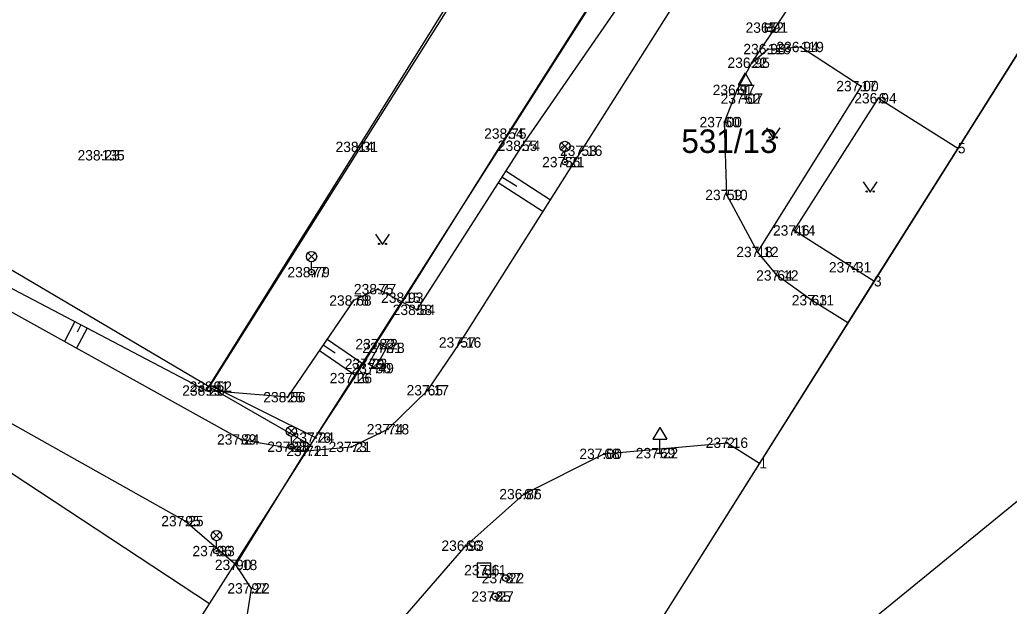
# Model space of a CAD drawing. Extents: x -645398 to -644998, y -1063322 to -1063031.
# Drawn here: x -645269.4 to -645197.8, y -1063193.6 to -1063151.2 of the extents above; entities that cross this region are included whole.
import ezdxf

# ---------------------------------------------------------------- set-up
doc = ezdxf.new("R2010")
doc.units = 0
for name, color, linetype in [('Bod', 7, 'Continuous'), ('Doplněk polohopisu', 7, 'Continuous'), ('Elektrický kabel', 7, 'Continuous'), ('Hranice KN pozemků', 7, 'Continuous'), ('Kanalizace', 7, 'Continuous'), ('Kultury', 7, 'Continuous'), ('Rozhraní ploch', 7, 'Continuous'), ('Stavby', 7, 'Continuous'), ('Sítě podzemní nerozlišené', 7, 'Continuous'), ('Vjezdy-vchody', 7, 'Continuous'), ('Výška', 7, 'Continuous'), ('Výškopis', 7, 'Continuous'), ('Čísla parcel', 7, 'Continuous'), ('Číslo bodu', 7, 'Continuous'), ('Šrafy', 7, 'Continuous')]:
    doc.layers.add(name, color=color, linetype=linetype)

msp = doc.modelspace()

# ---------------------------------------------------------------- linework, layer by layer
at = {"layer": 'Bod'}
for p, q in [((-645215.22, -1063151.75), (-645215.27, -1063151.7)), ((-645215.22, -1063151.75), (-645215.27, -1063151.8)), ((-645215.22, -1063151.75), (-645215.17, -1063151.7)), ((-645215.22, -1063151.75), (-645215.17, -1063151.8)), ((-645215.29, -1063153.3), (-645215.34, -1063153.25)), ((-645215.29, -1063153.3), (-645215.24, -1063153.25)), ((-645212.9, -1063153.15), (-645212.95, -1063153.1)), ((-645212.9, -1063153.15), (-645212.95, -1063153.2)), ((-645212.9, -1063153.15), (-645212.85, -1063153.1)), ((-645212.9, -1063153.15), (-645212.85, -1063153.2)), ((-645215.29, -1063153.3), (-645215.34, -1063153.35)), ((-645215.29, -1063153.3), (-645215.24, -1063153.35)), ((-645216.44, -1063154.29), (-645216.49, -1063154.24)), ((-645216.44, -1063154.29), (-645216.49, -1063154.34)), ((-645216.44, -1063154.29), (-645216.39, -1063154.24)), ((-645216.44, -1063154.29), (-645216.39, -1063154.34)), ((-645208.52, -1063155.98), (-645208.57, -1063155.93)), ((-645208.52, -1063155.98), (-645208.57, -1063156.03)), ((-645208.52, -1063155.98), (-645208.47, -1063155.93)), ((-645208.52, -1063155.98), (-645208.47, -1063156.03)), ((-645217.51, -1063156.26), (-645217.56, -1063156.21)), ((-645217.51, -1063156.26), (-645217.56, -1063156.31)), ((-645217.51, -1063156.26), (-645217.46, -1063156.21)), ((-645217.51, -1063156.26), (-645217.46, -1063156.31)), ((-645216.93, -1063156.89), (-645216.98, -1063156.84)), ((-645216.93, -1063156.89), (-645216.88, -1063156.84)), ((-645207.26, -1063156.86), (-645207.31, -1063156.81)), ((-645207.26, -1063156.86), (-645207.21, -1063156.81)), ((-645216.93, -1063156.89), (-645216.98, -1063156.94)), ((-645216.93, -1063156.89), (-645216.88, -1063156.94)), ((-645207.26, -1063156.86), (-645207.31, -1063156.91)), ((-645207.26, -1063156.86), (-645207.21, -1063156.91)), ((-645218.42, -1063158.59), (-645218.47, -1063158.54)), ((-645218.42, -1063158.59), (-645218.47, -1063158.64)), ((-645218.42, -1063158.59), (-645218.37, -1063158.54)), ((-645218.42, -1063158.59), (-645218.37, -1063158.64)), ((-645234.08, -1063159.42), (-645234.13, -1063159.37)), ((-645234.08, -1063159.42), (-645234.13, -1063159.47)), ((-645234.08, -1063159.42), (-645234.03, -1063159.37)), ((-645234.08, -1063159.42), (-645234.03, -1063159.47)), ((-645244.93, -1063160.38), (-645244.98, -1063160.33)), ((-645244.93, -1063160.38), (-645244.98, -1063160.43)), ((-645244.93, -1063160.38), (-645244.88, -1063160.33)), ((-645244.93, -1063160.38), (-645244.88, -1063160.43)), ((-645233.09, -1063160.3), (-645233.14, -1063160.25)), ((-645233.09, -1063160.3), (-645233.14, -1063160.35)), ((-645233.09, -1063160.3), (-645233.04, -1063160.25)), ((-645233.09, -1063160.3), (-645233.04, -1063160.35)), ((-645201.53, -1063160.47), (-645201.58, -1063160.42)), ((-645201.53, -1063160.47), (-645201.48, -1063160.42)), ((-645263.52, -1063160.99), (-645263.57, -1063160.94)), ((-645263.52, -1063160.99), (-645263.57, -1063161.04)), ((-645263.52, -1063160.99), (-645263.47, -1063160.94)), ((-645263.52, -1063160.99), (-645263.47, -1063161.04)), ((-645228.78, -1063160.66), (-645228.83, -1063160.61)), ((-645228.78, -1063160.66), (-645228.83, -1063160.71)), ((-645228.78, -1063160.66), (-645228.73, -1063160.61)), ((-645228.78, -1063160.66), (-645228.73, -1063160.71)), ((-645201.53, -1063160.47), (-645201.58, -1063160.52)), ((-645201.53, -1063160.47), (-645201.48, -1063160.52)), ((-645229.97, -1063161.48), (-645230.02, -1063161.43)), ((-645229.97, -1063161.48), (-645230.02, -1063161.53)), ((-645229.97, -1063161.48), (-645229.92, -1063161.43)), ((-645229.97, -1063161.48), (-645229.92, -1063161.53)), ((-645218.25, -1063163.86), (-645218.3, -1063163.81)), ((-645218.25, -1063163.86), (-645218.3, -1063163.91)), ((-645218.25, -1063163.86), (-645218.2, -1063163.81)), ((-645218.25, -1063163.86), (-645218.2, -1063163.91)), ((-645213.38, -1063166.43), (-645213.43, -1063166.38)), ((-645213.38, -1063166.43), (-645213.43, -1063166.48)), ((-645213.38, -1063166.43), (-645213.33, -1063166.38)), ((-645213.38, -1063166.43), (-645213.33, -1063166.48)), ((-645216.04, -1063167.99), (-645216.09, -1063167.94)), ((-645216.04, -1063167.99), (-645216.09, -1063168.04)), ((-645216.04, -1063167.99), (-645215.99, -1063167.94)), ((-645216.04, -1063167.99), (-645215.99, -1063168.04)), ((-645248.32, -1063169.45), (-645248.37, -1063169.4)), ((-645248.32, -1063169.45), (-645248.37, -1063169.5)), ((-645248.32, -1063169.45), (-645248.27, -1063169.4)), ((-645248.32, -1063169.45), (-645248.27, -1063169.5)), ((-645214.6, -1063169.69), (-645214.65, -1063169.64)), ((-645214.6, -1063169.69), (-645214.65, -1063169.74)), ((-645214.6, -1063169.69), (-645214.55, -1063169.64)), ((-645214.6, -1063169.69), (-645214.55, -1063169.74)), ((-645209.21, -1063169.1), (-645209.26, -1063169.05)), ((-645209.21, -1063169.1), (-645209.26, -1063169.15)), ((-645209.21, -1063169.1), (-645209.16, -1063169.05)), ((-645209.21, -1063169.1), (-645209.16, -1063169.15)), ((-645207.6, -1063170.11), (-645207.65, -1063170.06)), ((-645207.6, -1063170.11), (-645207.65, -1063170.16)), ((-645207.6, -1063170.11), (-645207.55, -1063170.06)), ((-645207.6, -1063170.11), (-645207.55, -1063170.16)), ((-645243.51, -1063170.68), (-645243.56, -1063170.63)), ((-645243.51, -1063170.68), (-645243.56, -1063170.73)), ((-645243.51, -1063170.68), (-645243.46, -1063170.63)), ((-645243.51, -1063170.68), (-645243.46, -1063170.73)), ((-645245.27, -1063171.5), (-645245.32, -1063171.45)), ((-645245.27, -1063171.5), (-645245.32, -1063171.55)), ((-645245.27, -1063171.5), (-645245.22, -1063171.45)), ((-645245.27, -1063171.5), (-645245.22, -1063171.55)), ((-645241.54, -1063171.3), (-645241.59, -1063171.25)), ((-645241.54, -1063171.3), (-645241.59, -1063171.35)), ((-645241.54, -1063171.3), (-645241.49, -1063171.25)), ((-645241.54, -1063171.3), (-645241.49, -1063171.35)), ((-645212.11, -1063171.48), (-645212.16, -1063171.43)), ((-645212.11, -1063171.48), (-645212.16, -1063171.53)), ((-645212.11, -1063171.48), (-645212.06, -1063171.43)), ((-645212.11, -1063171.48), (-645212.06, -1063171.53)), ((-645240.7, -1063172.18), (-645240.75, -1063172.13)), ((-645240.7, -1063172.18), (-645240.75, -1063172.23)), ((-645240.7, -1063172.18), (-645240.65, -1063172.13)), ((-645240.7, -1063172.18), (-645240.65, -1063172.23)), ((-645243.4, -1063174.66), (-645243.45, -1063174.61)), ((-645243.4, -1063174.66), (-645243.45, -1063174.71)), ((-645243.4, -1063174.66), (-645243.35, -1063174.61)), ((-645243.4, -1063174.66), (-645243.35, -1063174.71)), ((-645237.55, -1063174.54), (-645237.6, -1063174.49)), ((-645237.55, -1063174.54), (-645237.6, -1063174.59)), ((-645237.55, -1063174.54), (-645237.5, -1063174.49)), ((-645237.55, -1063174.54), (-645237.5, -1063174.59)), ((-645242.9, -1063174.93), (-645242.95, -1063174.88)), ((-645242.9, -1063174.93), (-645242.95, -1063174.98)), ((-645242.9, -1063174.93), (-645242.85, -1063174.88)), ((-645242.9, -1063174.93), (-645242.85, -1063174.98)), ((-645244.17, -1063176.09), (-645244.22, -1063176.04)), ((-645244.17, -1063176.09), (-645244.22, -1063176.14)), ((-645244.17, -1063176.09), (-645244.12, -1063176.04)), ((-645244.17, -1063176.09), (-645244.12, -1063176.14)), ((-645243.68, -1063176.4), (-645243.73, -1063176.35)), ((-645243.68, -1063176.4), (-645243.73, -1063176.45)), ((-645243.68, -1063176.4), (-645243.63, -1063176.35)), ((-645243.68, -1063176.4), (-645243.63, -1063176.45)), ((-645245.24, -1063177.12), (-645245.29, -1063177.07)), ((-645245.24, -1063177.12), (-645245.29, -1063177.17)), ((-645245.24, -1063177.12), (-645245.19, -1063177.07)), ((-645245.24, -1063177.12), (-645245.19, -1063177.17)), ((-645255.94, -1063178.02), (-645255.99, -1063177.97)), ((-645255.94, -1063178.02), (-645255.99, -1063178.07)), ((-645255.94, -1063178.02), (-645255.89, -1063177.97)), ((-645255.94, -1063178.02), (-645255.89, -1063178.07)), ((-645255.41, -1063177.74), (-645255.46, -1063177.69)), ((-645255.41, -1063177.74), (-645255.46, -1063177.79)), ((-645255.41, -1063177.74), (-645255.36, -1063177.69)), ((-645255.41, -1063177.74), (-645255.36, -1063177.79)), ((-645239.91, -1063178), (-645239.96, -1063177.95)), ((-645239.91, -1063178), (-645239.96, -1063178.05)), ((-645239.91, -1063178), (-645239.86, -1063177.95)), ((-645239.91, -1063178), (-645239.86, -1063178.05)), ((-645250.05, -1063178.5), (-645250.1, -1063178.45)), ((-645250.05, -1063178.5), (-645250.1, -1063178.55)), ((-645250.05, -1063178.5), (-645250, -1063178.45)), ((-645250.05, -1063178.5), (-645250, -1063178.55)), ((-645242.79, -1063180.82), (-645242.84, -1063180.77)), ((-645242.79, -1063180.82), (-645242.84, -1063180.87)), ((-645242.79, -1063180.82), (-645242.74, -1063180.77)), ((-645242.79, -1063180.82), (-645242.74, -1063180.87)), ((-645253.42, -1063181.56), (-645253.47, -1063181.51)), ((-645253.42, -1063181.56), (-645253.47, -1063181.61)), ((-645253.42, -1063181.56), (-645253.37, -1063181.51)), ((-645253.42, -1063181.56), (-645253.37, -1063181.61)), ((-645248.02, -1063181.43), (-645248.07, -1063181.38)), ((-645248.02, -1063181.43), (-645248.07, -1063181.48)), ((-645248.02, -1063181.43), (-645247.97, -1063181.38)), ((-645248.02, -1063181.43), (-645247.97, -1063181.48)), ((-645218.23, -1063181.8), (-645218.28, -1063181.75)), ((-645218.23, -1063181.8), (-645218.28, -1063181.85)), ((-645218.23, -1063181.8), (-645218.18, -1063181.75)), ((-645218.23, -1063181.8), (-645218.18, -1063181.85)), ((-645249.78, -1063182.09), (-645249.83, -1063182.04)), ((-645249.78, -1063182.09), (-645249.83, -1063182.14)), ((-645249.78, -1063182.09), (-645249.73, -1063182.04)), ((-645249.78, -1063182.09), (-645249.73, -1063182.14)), ((-645248.71, -1063182.39), (-645248.76, -1063182.34)), ((-645248.71, -1063182.39), (-645248.76, -1063182.44)), ((-645248.71, -1063182.39), (-645248.66, -1063182.34)), ((-645248.71, -1063182.39), (-645248.66, -1063182.44)), ((-645245.43, -1063182.1), (-645245.48, -1063182.05)), ((-645245.43, -1063182.1), (-645245.48, -1063182.15)), ((-645245.43, -1063182.1), (-645245.38, -1063182.05)), ((-645245.43, -1063182.1), (-645245.38, -1063182.15)), ((-645227.12, -1063182.6), (-645227.17, -1063182.55)), ((-645227.12, -1063182.6), (-645227.17, -1063182.65)), ((-645227.12, -1063182.6), (-645227.07, -1063182.55)), ((-645227.12, -1063182.6), (-645227.07, -1063182.65)), ((-645223.1, -1063182.55), (-645223.15, -1063182.5)), ((-645223.1, -1063182.55), (-645223.15, -1063182.6)), ((-645223.1, -1063182.55), (-645223.05, -1063182.5)), ((-645223.1, -1063182.55), (-645223.05, -1063182.6)), ((-645215.89, -1063183.28), (-645215.94, -1063183.23)), ((-645215.89, -1063183.28), (-645215.94, -1063183.33)), ((-645215.89, -1063183.28), (-645215.84, -1063183.23)), ((-645215.89, -1063183.28), (-645215.84, -1063183.33)), ((-645232.94, -1063185.52), (-645232.99, -1063185.47)), ((-645232.94, -1063185.52), (-645232.89, -1063185.47)), ((-645232.94, -1063185.52), (-645232.99, -1063185.57)), ((-645232.94, -1063185.52), (-645232.89, -1063185.57)), ((-645257.46, -1063187.47), (-645257.51, -1063187.42)), ((-645257.46, -1063187.47), (-645257.51, -1063187.52)), ((-645257.46, -1063187.47), (-645257.41, -1063187.42)), ((-645257.46, -1063187.47), (-645257.41, -1063187.52)), ((-645255.2, -1063189.64), (-645255.25, -1063189.59)), ((-645255.2, -1063189.64), (-645255.25, -1063189.69)), ((-645255.2, -1063189.64), (-645255.15, -1063189.59)), ((-645255.2, -1063189.64), (-645255.15, -1063189.69)), ((-645237.15, -1063189.25), (-645237.2, -1063189.2)), ((-645237.15, -1063189.25), (-645237.2, -1063189.3)), ((-645237.15, -1063189.25), (-645237.1, -1063189.2)), ((-645237.15, -1063189.25), (-645237.1, -1063189.3)), ((-645253.79, -1063190.64), (-645253.84, -1063190.59)), ((-645253.79, -1063190.64), (-645253.84, -1063190.69)), ((-645253.79, -1063190.64), (-645253.74, -1063190.59)), ((-645253.79, -1063190.64), (-645253.74, -1063190.69)), ((-645235.83, -1063191.02), (-645235.88, -1063190.97)), ((-645235.83, -1063191.02), (-645235.88, -1063191.07)), ((-645235.83, -1063191.02), (-645235.78, -1063190.97)), ((-645235.83, -1063191.02), (-645235.78, -1063191.07)), ((-645234.25, -1063191.6), (-645234.3, -1063191.55)), ((-645234.25, -1063191.6), (-645234.3, -1063191.65)), ((-645234.25, -1063191.6), (-645234.2, -1063191.55)), ((-645234.25, -1063191.6), (-645234.2, -1063191.65)), ((-645252.67, -1063192.34), (-645252.72, -1063192.29)), ((-645252.67, -1063192.34), (-645252.72, -1063192.39)), ((-645252.67, -1063192.34), (-645252.62, -1063192.29)), ((-645252.67, -1063192.34), (-645252.62, -1063192.39)), ((-645235, -1063192.93), (-645235.05, -1063192.88)), ((-645235, -1063192.93), (-645235.05, -1063192.98)), ((-645235, -1063192.93), (-645234.95, -1063192.88)), ((-645235, -1063192.93), (-645234.95, -1063192.98))]:
    msp.add_line(p, q, dxfattribs=at)
at = {"layer": 'Doplněk polohopisu'}
for p, q in [((-645216.93, -1063155.024), (-645217.43, -1063155.89)), ((-645216.93, -1063155.024), (-645216.43, -1063155.89)), ((-645217.43, -1063155.89), (-645216.43, -1063155.89)), ((-645216.93, -1063156.89), (-645216.93, -1063155.89)), ((-645217.18, -1063156.89), (-645216.68, -1063156.89)), ((-645223.1, -1063180.684), (-645223.6, -1063181.55)), ((-645223.1, -1063180.684), (-645222.6, -1063181.55)), ((-645223.6, -1063181.55), (-645222.6, -1063181.55)), ((-645223.1, -1063182.55), (-645223.1, -1063181.55)), ((-645223.35, -1063182.55), (-645222.85, -1063182.55))]:
    msp.add_line(p, q, dxfattribs=at)
msp.add_lwpolyline([(-645255.41, -1063177.74), (-645248.02, -1063181.43), (-645245.24, -1063177.12), (-645241.54, -1063171.3), (-645234.08, -1063159.42), (-645213.53, -1063127.04)], dxfattribs=at)
at = {"layer": 'Elektrický kabel'}
for p, q in [((-645230.234, -1063160.618), (-645229.706, -1063160.09)), ((-645229.698, -1063160.615), (-645230.226, -1063160.086)), ((-645229.97, -1063161.28), (-645229.97, -1063160.73)), ((-645248.584, -1063168.588), (-645248.056, -1063168.06)), ((-645248.048, -1063168.585), (-645248.576, -1063168.056)), ((-645248.32, -1063169.25), (-645248.32, -1063168.7)), ((-645250.044, -1063181.228), (-645249.516, -1063180.7)), ((-645249.508, -1063181.225), (-645250.036, -1063180.696)), ((-645249.78, -1063181.89), (-645249.78, -1063181.34)), ((-645255.464, -1063188.778), (-645254.936, -1063188.25)), ((-645254.928, -1063188.775), (-645255.456, -1063188.246)), ((-645255.2, -1063189.44), (-645255.2, -1063188.89))]:
    msp.add_line(p, q, dxfattribs=at)
for centre, radius in [((-645229.97, -1063160.355), 0.375), ((-645229.97, -1063161.48), 0.2), ((-645248.32, -1063168.325), 0.375), ((-645248.32, -1063169.45), 0.2), ((-645249.78, -1063180.965), 0.375), ((-645249.78, -1063182.09), 0.2), ((-645255.2, -1063188.515), 0.375), ((-645255.2, -1063189.64), 0.2), ((-645234.25, -1063191.6), 0.25), ((-645235, -1063192.93), 0.25)]:
    msp.add_circle(centre, radius, dxfattribs=at)
at = {"layer": 'Hranice KN pozemků'}
for p, q in [((-645177.04, -1063121.61), (-645236.42, -1063215.87)), ((-645248.4, -1063181.97), (-645213.42, -1063127.02)), ((-645226.33, -1063131.14), (-645255.73, -1063177.75)), ((-645255.73, -1063177.75), (-645319.16, -1063140.34)), ((-645255.71, -1063193.46), (-645318.7, -1063152.02)), ((-645170.69, -1063164.36), (-645221.27, -1063205.67)), ((-645248.4, -1063181.97), (-645255.73, -1063177.75)), ((-645255.71, -1063193.46), (-645248.4, -1063181.97))]:
    msp.add_line(p, q, dxfattribs=at)
msp.add_lwpolyline([(-645275.52, -1063231.85), (-645275.24, -1063226.82), (-645267.15, -1063211.42), (-645255.71, -1063193.46)], dxfattribs=at)
at = {"layer": 'Kanalizace'}
msp.add_line((-645215.47, -1063151.75), (-645214.97, -1063151.75), dxfattribs=at)
msp.add_lwpolyline([(-645215.47, -1063152), (-645214.97, -1063152), (-645214.97, -1063151.5), (-645215.47, -1063151.5)], close=True, dxfattribs=at)
at = {"layer": 'Kultury'}
for points in [[(-645215.389, -1063158.998), (-645214.889, -1063159.748), (-645214.389, -1063158.998)], [(-645208.369, -1063162.911), (-645207.869, -1063163.661), (-645207.369, -1063162.911)], [(-645243.679, -1063166.705), (-645243.179, -1063167.455), (-645242.679, -1063166.705)]]:
    msp.add_lwpolyline(points, dxfattribs=at)
for centre in [(-645215.139, -1063159.698), (-645214.639, -1063159.698), (-645208.119, -1063163.611), (-645207.619, -1063163.611), (-645243.429, -1063167.405), (-645242.929, -1063167.405)]:
    msp.add_circle(centre, 0.05, dxfattribs=at)
at = {"layer": 'Rozhraní ploch'}
for points in [[(-645324.89, -1063137.57), (-645306.17, -1063108.34), (-645294.16, -1063089.19), (-645266.49, -1063106.33), (-645238.82, -1063123.47), (-645226.63, -1063131.07), (-645233.92, -1063142.75), (-645244.93, -1063160.38), (-645255.94, -1063178.02)], [(-645339.9, -1063127.53), (-645339.17, -1063128.33), (-645324.89, -1063137.57), (-645316.1, -1063143.14), (-645308.22, -1063148.13), (-645296.87, -1063155.59), (-645287.5, -1063161.41), (-645276.29, -1063168.88), (-645253.42, -1063181.56), (-645248.71, -1063182.39), (-645245.43, -1063182.1), (-645242.79, -1063180.82), (-645239.91, -1063178), (-645237.55, -1063174.54), (-645228.78, -1063160.66), (-645221.44, -1063149.07), (-645216.34, -1063141.49), (-645207.45, -1063129.62)], [(-645209.494, -1063173.126), (-645212.11, -1063171.48), (-645214.6, -1063169.69), (-645216.04, -1063167.99), (-645218.25, -1063163.86), (-645218.42, -1063158.59), (-645217.51, -1063156.26), (-645216.44, -1063154.29), (-645209.71, -1063144.2), (-645203.75, -1063135.58)], [(-645254.393, -1063244.443), (-645260.09, -1063240.57), (-645273.68, -1063231.95), (-645253.9, -1063200.2), (-645252.67, -1063192.34), (-645253.79, -1063190.64), (-645257.46, -1063187.47), (-645280.34, -1063174.63), (-645291.34, -1063167.5), (-645316.22, -1063151.47), (-645336.53, -1063139.24)], [(-645216.44, -1063154.29), (-645215.286, -1063153.303), (-645212.9, -1063153.15), (-645208.52, -1063155.98), (-645216.04, -1063167.99)], [(-645207.6, -1063170.11), (-645209.21, -1063169.1), (-645213.38, -1063166.43), (-645207.26, -1063156.86), (-645201.53, -1063160.47)], [(-645276.29, -1063168.88), (-645275.73, -1063167.65), (-645255.94, -1063178.02)], [(-645249.444, -1063236.581), (-645253.31, -1063234.14), (-645257.66, -1063228.97), (-645256.88, -1063217.85), (-645247.18, -1063202.58), (-645242.79, -1063195.77), (-645237.15, -1063189.25), (-645232.94, -1063185.52), (-645227.12, -1063182.6), (-645218.23, -1063181.8), (-645215.89, -1063183.28)]]:
    msp.add_lwpolyline(points, dxfattribs=at)
at = {"layer": 'Stavby'}
for p, q in [((-645177.047, -1063121.573), (-645201.529, -1063160.465)), ((-645201.529, -1063160.465), (-645207.603, -1063170.113)), ((-645207.603, -1063170.113), (-645215.889, -1063183.277)), ((-645243.4, -1063174.66), (-645244.17, -1063176.09)), ((-645242.9, -1063174.93), (-645243.4, -1063174.66)), ((-645243.68, -1063176.4), (-645242.9, -1063174.93)), ((-645244.17, -1063176.09), (-645243.68, -1063176.4)), ((-645215.889, -1063183.277), (-645249.444, -1063236.581))]:
    msp.add_line(p, q, dxfattribs=at)
at = {"layer": 'Sítě podzemní nerozlišené'}
for p, q in [((-645235.33, -1063190.52), (-645236.33, -1063190.52)), ((-645236.33, -1063190.52), (-645236.33, -1063191.52)), ((-645235.33, -1063191.52), (-645235.33, -1063190.52)), ((-645236.33, -1063191.52), (-645235.33, -1063191.52))]:
    msp.add_line(p, q, dxfattribs=at)
at = {"layer": 'Vjezdy-vchody'}
msp.add_line((-645253.79, -1063190.64), (-645248.71, -1063182.39), dxfattribs=at)
at = {"layer": 'Výškopis'}
msp.add_lwpolyline([(-645211.28, -1063128.08), (-645218.64, -1063139.36), (-645233.09, -1063160.3), (-645240.7, -1063172.18), (-645243.51, -1063170.68), (-645245.27, -1063171.5), (-645250.05, -1063178.5), (-645255.94, -1063178.02)], dxfattribs=at)
at = {"layer": 'Šrafy'}
for p, q in [((-645234.53, -1063162.548), (-645233.463, -1063163.232)), ((-645234.26, -1063162.127), (-645231.019, -1063164.203)), ((-645234.8, -1063162.969), (-645231.553, -1063165.049)), ((-645265.454, -1063173.032), (-645266.207, -1063174.47)), ((-645265.011, -1063173.264), (-645265.283, -1063173.784)), ((-645264.568, -1063173.496), (-645265.332, -1063174.955)), ((-645247.466, -1063174.718), (-645246.616, -1063175.299)), ((-645247.184, -1063174.305), (-645244.581, -1063176.083)), ((-645247.748, -1063175.131), (-645245.117, -1063176.927))]:
    msp.add_line(p, q, dxfattribs=at)

# ---------------------------------------------------------------- texts
at = {"layer": 'Výška'}
for s, p in [('236.91', (-645216.897, -1063152.125)), ('236.93', (-645217.056, -1063153.675)), ('236.94', (-645214.666, -1063153.525)), ('236.95', (-645218.206, -1063154.665)), ('236.97', (-645219.276, -1063156.635)), ('237.00', (-645210.327, -1063156.355)), ('237.07', (-645218.704, -1063157.265)), ('236.94', (-645209.026, -1063157.235)), ('237.00', (-645220.227, -1063158.965)), ('238.75', (-645235.822, -1063159.795)), ('238.31', (-645246.583, -1063160.755)), ('238.74', (-645234.832, -1063160.675)), ('237.16', (-645230.33, -1063161.035)), ('238.23', (-645265.262, -1063161.365)), ('237.21', (-645231.623, -1063161.855)), ('237.10', (-645219.812, -1063164.235)), ('237.14', (-645214.909, -1063166.805)), ('237.12', (-645217.569, -1063168.365)), ('237.31', (-645210.863, -1063169.475)), ('238.79', (-645250.065, -1063169.825)), ('237.12', (-645216.129, -1063170.065)), ('238.77', (-645245.252, -1063171.055)), ('238.68', (-645247.033, -1063171.875)), ('238.93', (-645243.285, -1063171.675)), ('237.11', (-645213.551, -1063171.855)), ('238.84', (-645242.442, -1063172.555)), ('237.72', (-645245.142, -1063175.035)), ('237.78', (-645244.642, -1063175.305)), ('237.16', (-645239.1, -1063174.915)), ('237.23', (-645245.912, -1063176.465)), ('237.49', (-645245.425, -1063176.775)), ('237.26', (-645247.003, -1063177.495)), ('238.52', (-645257.152, -1063178.115)), ('237.17', (-645241.439, -1063178.375)), ('238.28', (-645257.682, -1063178.395)), ('238.56', (-645251.813, -1063178.875)), ('237.18', (-645244.319, -1063181.195)), ('237.24', (-645255.162, -1063181.935)), ('237.24', (-645249.762, -1063181.805)), ('237.28', (-645251.522, -1063182.465)), ('237.21', (-645247.083, -1063182.475)), ('237.16', (-645219.78, -1063182.175)), ('237.11', (-645250.151, -1063182.765)), ('237.00', (-645228.927, -1063182.975)), ('237.22', (-645224.842, -1063182.925)), ('236.86', (-645234.723, -1063185.895)), ('237.25', (-645259.202, -1063187.845)), ('236.93', (-645238.916, -1063189.625)), ('237.33', (-645256.942, -1063190.015)), ('237.18', (-645255.319, -1063191.015)), ('237.11', (-645237.271, -1063191.395)), ('237.22', (-645235.992, -1063191.975)), ('237.22', (-645254.412, -1063192.715)), ('237.27', (-645236.742, -1063193.305))]:
    msp.add_text(s, height=0.75, dxfattribs=at).set_placement(p)
at = {"layer": 'Čísla parcel'}
msp.add_text('531/13', height=1.7, dxfattribs=at).set_placement((-645221.54, -1063160.82))
at = {"layer": 'Číslo bodu'}
for s, p in [('52', (-645215.22, -1063152.125)), ('118', (-645215.29, -1063153.675)), ('119', (-645212.9, -1063153.525)), ('22', (-645216.44, -1063154.665)), ('61', (-645217.51, -1063156.635)), ('17', (-645208.52, -1063156.355)), ('62', (-645216.93, -1063157.265)), ('6', (-645207.26, -1063157.235)), ('60', (-645218.42, -1063158.965)), ('54', (-645234.08, -1063159.795)), ('14', (-645244.93, -1063160.755)), ('55', (-645233.09, -1063160.675)), ('53', (-645228.78, -1063161.035)), ('5', (-645201.53, -1063160.845)), ('135', (-645263.52, -1063161.365)), ('56', (-645229.97, -1063161.855)), ('59', (-645218.25, -1063164.235)), ('46', (-645213.38, -1063166.805)), ('18', (-645216.04, -1063168.365)), ('4', (-645209.21, -1063169.475)), ('77', (-645248.32, -1063169.825)), ('64', (-645214.6, -1063170.065)), ('3', (-645207.6, -1063170.485)), ('75', (-645243.51, -1063171.055)), ('78', (-645245.27, -1063171.875)), ('15', (-645241.54, -1063171.675)), ('63', (-645212.11, -1063171.855)), ('58', (-645240.7, -1063172.555)), ('82', (-645243.4, -1063175.035)), ('81', (-645242.9, -1063175.305)), ('57', (-645237.55, -1063174.915)), ('79', (-645244.17, -1063176.465)), ('80', (-645243.68, -1063176.775)), ('16', (-645245.24, -1063177.495)), ('91', (-645255.41, -1063178.115)), ('65', (-645239.91, -1063178.375)), ('13', (-645255.94, -1063178.395)), ('25', (-645250.05, -1063178.875)), ('74', (-645242.79, -1063181.195)), ('89', (-645253.42, -1063181.935)), ('76', (-645248.02, -1063181.805)), ('88', (-645249.78, -1063182.465)), ('73', (-645245.43, -1063182.475)), ('2', (-645218.23, -1063182.175)), ('72', (-645248.71, -1063182.765)), ('68', (-645227.12, -1063182.975)), ('69', (-645223.1, -1063182.925)), ('1', (-645215.89, -1063183.655)), ('67', (-645232.94, -1063185.895)), ('95', (-645257.46, -1063187.845)), ('66', (-645237.15, -1063189.625)), ('96', (-645255.2, -1063190.015)), ('90', (-645253.79, -1063191.015)), ('86', (-645235.83, -1063191.395)), ('87', (-645234.25, -1063191.975)), ('97', (-645252.67, -1063192.715)), ('85', (-645235, -1063193.305))]:
    msp.add_text(s, height=0.75, dxfattribs=at).set_placement(p)

doc.saveas('drawing.dxf')
